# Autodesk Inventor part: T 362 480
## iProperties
Created: 2006-04
Material: 6PA45/1GF30
Document SubType Name: Modeling
Designer: I.Baliuc
Part Number: T 362 480
Description: Haubenbefestigung
Density: 1.14 g/cm^3
Title: Haubenbefestigung
Company: Mayer & Müller AG Schaltgeräte
Zweck: DC-Schalter
Author: T.Messerschmitt
Keywords: 362432
Revision Number: 362480
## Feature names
1. Extrusion4
2. Bohrung_Ø6.2 [Hole]
3. Bohrung_M6 [Hole]
4. Bezeichnung2 [Tagging]
